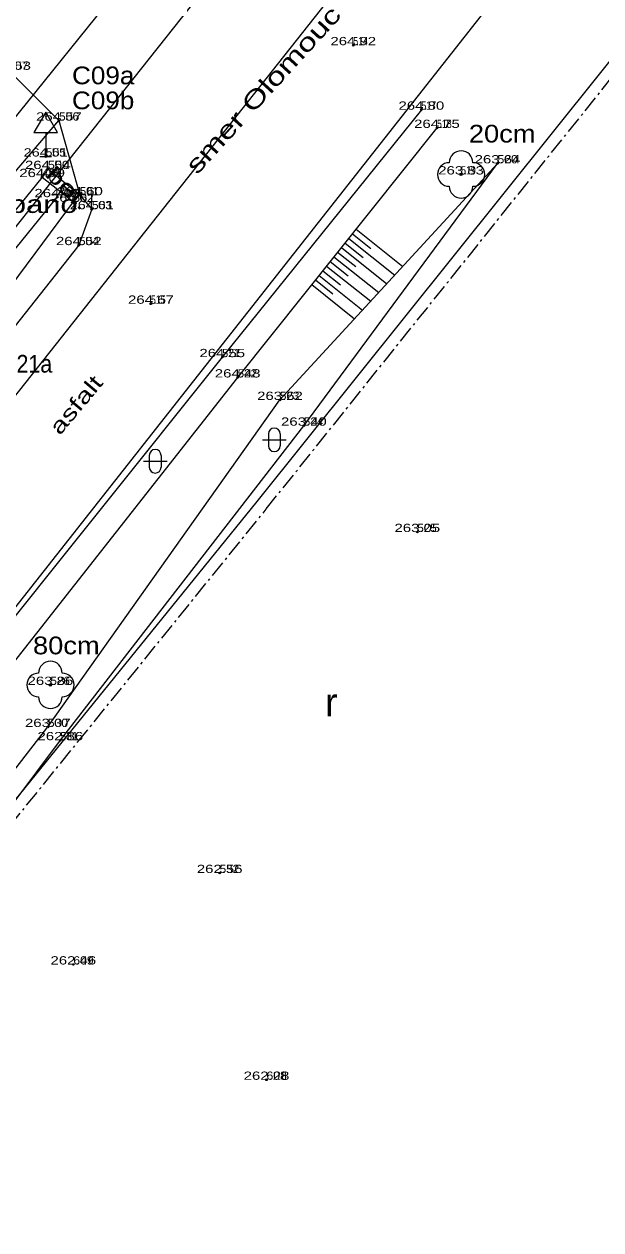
# Model space of a CAD drawing. Extents: x -568530 to -568223, y -1154101 to -1153740.
# Drawn here: x -568358.2 to -568333.8, y -1153886.3 to -1153835.3 of the extents above; entities that cross this region are included whole.
import ezdxf
from ezdxf.enums import TextEntityAlignment as Align

# ---------------------------------------------------------------- set-up
doc = ezdxf.new("R2010")
doc.units = 0
doc.header["$LTSCALE"] = 0.14
doc.header["$PDMODE"] = 32
doc.header["$PDSIZE"] = 0.07
doc.linetypes.add('DOT_DASHED', pattern=[7.7, 5, -1.2, 0.3, -1.2])
for name, color, linetype, lineweight in [('1', 7, 'Continuous', 25), ('10', 7, 'Continuous', 13), ('11', 7, 'Continuous', 13), ('12', 7, 'Continuous', 13), ('14', 7, 'Continuous', 13), ('15', 7, 'Continuous', 13), ('22', 7, 'Continuous', 13), ('23', 7, 'Continuous', 13), ('34', 7, 'Continuous', 13), ('36', 7, 'Continuous', 13), ('4', 7, 'Continuous', 25), ('42', 7, 'Continuous', 13), ('6', 7, 'DOT_DASHED', 25)]:
    doc.layers.add(name, color=color, linetype=linetype, lineweight=lineweight)
doc.layers.add('13', color=7, linetype='Continuous')
doc.layers.add('40', color=7, linetype='Continuous')

msp = doc.modelspace()

# ---------------------------------------------------------------- linework, layer by layer
at = {"layer": '1'}
for points in [[(-568412.56, -1153907.8), (-568411.98, -1153907.12), (-568411.65, -1153906.73), (-568402.04, -1153895.41), (-568393.94, -1153886.59), (-568382.28, -1153873.78), (-568334.11, -1153813.06), (-568281.93, -1153748.16)], [(-568397.85, -1153916.62), (-568348.36, -1153855.52), (-568306.73, -1153803.52), (-568266.23, -1153754.08)], [(-568359.48, -1153840.35), (-568353.42, -1153832.84), (-568366.2, -1153822.48), (-568392.31, -1153801.22), (-568392.76, -1153800.31), (-568393.76, -1153795.28)]]:
    msp.add_lwpolyline(points, dxfattribs=at)
at = {"layer": '10'}
for points in [[(-568358.89, -1153837.25), (-568356.74, -1153839.4), (-568355.85, -1153842.56), (-568355.35, -1153843.15), (-568355.9, -1153844.67)], [(-568341.41, -1153838.94), (-568349.83, -1153849.41), (-568360.25, -1153862.43), (-568369.78, -1153874.42), (-568378.19, -1153884.73), (-568386.01, -1153894.27), (-568392.67, -1153902.27), (-568398.22, -1153909.37), (-568401.79, -1153914.15), (-568403.6, -1153916.28)], [(-568355.9, -1153844.67), (-568366.36, -1153857.91), (-568375.7, -1153869.7), (-568384.23, -1153880.16)]]:
    msp.add_lwpolyline(points, dxfattribs=at)
at = {"layer": '11'}
msp.add_lwpolyline([(-568381.7, -1153869.78), (-568379.23, -1153866.82), (-568369.76, -1153855.31), (-568359.16, -1153842.23), (-568356.74, -1153839.4)], dxfattribs=at)
msp.add_lwpolyline([(-568356.13, -1153842.84), (-568355.85, -1153842.56), (-568357.21, -1153841.45), (-568357.45, -1153841.79)], close=True, dxfattribs=at)
for p in [(-568344.29, -1153836.21), (-568356.74, -1153839.4), (-568341.41, -1153838.94), (-568340.75, -1153839.71), (-568357.3, -1153840.92), (-568357.21, -1153841.45), (-568338.19, -1153841.21), (-568357.45, -1153841.79), (-568339.73, -1153841.68), (-568356.81, -1153842.64), (-568356.13, -1153842.84), (-568355.85, -1153842.56), (-568355.35, -1153843.15), (-568355.9, -1153844.67), (-568352.85, -1153847.15), (-568349.83, -1153849.41), (-568349.18, -1153850.27), (-568347.39, -1153851.22), (-568346.38, -1153852.31), (-568341.58, -1153856.81), (-568357.1, -1153863.28), (-568357.21, -1153865.06), (-568356.68, -1153865.62), (-568349.94, -1153871.24), (-568356.13, -1153875.11), (-568347.96, -1153879.99)]:
    msp.add_point(p, dxfattribs=at)
at = {"layer": '14'}
for points in [[(-568340.75, -1153839.71), (-568349.18, -1153850.27), (-568359.47, -1153863.33), (-568369.12, -1153875.21), (-568377.44, -1153885.3)], [(-568395.11, -1153912.31), (-568389.39, -1153905.01), (-568382.04, -1153896.57), (-568374.93, -1153888.14), (-568366.7, -1153877.32), (-568357.21, -1153865.06), (-568347.39, -1153851.22), (-568338.19, -1153841.21)], [(-568357.45, -1153841.79), (-568368.95, -1153855.98), (-568378.18, -1153867.7), (-568386.1, -1153877.81), (-568384.71, -1153879.25), (-568384.84, -1153877.95), (-568386.1, -1153877.81)], [(-568384.84, -1153877.95), (-568377.13, -1153868.43), (-568368.18, -1153856.68), (-568356.81, -1153842.64)], [(-568384.71, -1153879.25), (-568376.25, -1153869.09), (-568366.96, -1153857.43), (-568356.13, -1153842.84)]]:
    msp.add_lwpolyline(points, dxfattribs=at)
at = {"layer": '15'}
for p, q in [((-568344.482, -1153844.385), (-568342.536, -1153845.939)), ((-568344.326, -1153844.19), (-568343.542, -1153844.815)), ((-568344.17, -1153843.994), (-568342.197, -1153845.57)), ((-568344.95, -1153844.971), (-568344.188, -1153845.58)), ((-568344.794, -1153844.776), (-568342.875, -1153846.308)), ((-568344.638, -1153844.58), (-568343.865, -1153845.197)), ((-568345.262, -1153845.362), (-568344.511, -1153845.962)), ((-568345.106, -1153845.167), (-568343.214, -1153846.677)), ((-568345.73, -1153845.948), (-568343.893, -1153847.415)), ((-568345.574, -1153845.753), (-568344.834, -1153846.344)), ((-568345.418, -1153845.557), (-568343.553, -1153847.046)), ((-568346.042, -1153846.339), (-568344.232, -1153847.784)), ((-568345.886, -1153846.143), (-568345.156, -1153846.726))]:
    msp.add_line(p, q, dxfattribs=at)
at = {"layer": '22'}
for centre in [(-568339.73, -1153841.68), (-568357.1, -1153863.28)]:
    msp.add_circle(centre, 0.05, dxfattribs=at)
for centre, start, end in [((-568339.73, -1153841.18), 0, 180), ((-568340.23, -1153841.68), 90, 270), ((-568339.23, -1153841.68), 270, 90), ((-568339.73, -1153842.18), 180, 0), ((-568357.1, -1153862.78), 0, 180), ((-568357.6, -1153863.28), 90, 270), ((-568356.6, -1153863.28), 270, 90), ((-568357.1, -1153863.78), 180, 0)]:
    msp.add_arc(centre, 0.5, start, end, dxfattribs=at)
at = {"layer": '23'}
msp.add_lwpolyline([(-568354.04, -1153929.41), (-568364.61, -1153923.44), (-568379.16, -1153915.86), (-568390.37, -1153909.46), (-568387.81, -1153906.15), (-568381.36, -1153897.16), (-568374.28, -1153888.42), (-568365.82, -1153877.84), (-568356.68, -1153865.62), (-568346.38, -1153852.31), (-568338.19, -1153841.21)], dxfattribs=at)
at = {"layer": '34'}
for p, q in [((-568357.3, -1153839.902), (-568357.3, -1153840.92)), ((-568357.55, -1153840.92), (-568357.05, -1153840.92))]:
    msp.add_line(p, q, dxfattribs=at)
msp.add_lwpolyline([(-568357.8, -1153839.902), (-568356.8, -1153839.902), (-568357.3, -1153839.036)], close=True, dxfattribs=at)
at = {"layer": '36'}
for p, q in [((-568348.132, -1153852.907), (-568347.132, -1153852.907)), ((-568347.882, -1153852.657), (-568347.882, -1153853.157)), ((-568347.382, -1153852.657), (-568347.382, -1153853.157)), ((-568352.918, -1153853.565), (-568352.918, -1153854.065)), ((-568352.418, -1153853.565), (-568352.418, -1153854.065)), ((-568353.168, -1153853.815), (-568352.168, -1153853.815))]:
    msp.add_line(p, q, dxfattribs=at)
for centre, start, end in [((-568347.6321, -1153852.6587), 0, 180), ((-568352.6682, -1153853.5671), 0, 180), ((-568347.6321, -1153853.1587), 180, 0), ((-568352.6682, -1153854.0671), 180, 0)]:
    msp.add_arc(centre, 0.25, start, end, dxfattribs=at)
at = {"layer": '4'}
for points in [[(-568271.05, -1153741.89), (-568310.68, -1153791.16), (-568343.12, -1153831.47), (-568381.67, -1153880.2), (-568407.5, -1153911.44)], [(-568401.59, -1153914.63), (-568397.99, -1153910.05), (-568332.4, -1153826.72), (-568306.48, -1153794.28), (-568270.78, -1153751.53)]]:
    msp.add_lwpolyline(points, dxfattribs=at)
at = {"layer": '6'}
for p, q in [((-568347.97, -1153855.83), (-568306.34, -1153803.83)), ((-568390.25, -1153908.12), (-568347.97, -1153855.84))]:
    msp.add_line(p, q, dxfattribs=at)

# ---------------------------------------------------------------- texts
at = {"layer": '12'}
for s, width, p in [('264.92', 1.35, (-568344.29, -1153836.21)), ('264.53', 1.35, (-568358.89, -1153837.25)), ('264.80', 1.35, (-568341.4095, -1153838.94)), ('264.57', 1.35, (-568356.74, -1153839.4)), ('264.75', 1.35, (-568340.7505, -1153839.71)), ('264.51', 1.3, (-568357.3, -1153840.92)), ('263.64', 1.35, (-568338.19, -1153841.21)), ('264.54', 1.35, (-568357.21, -1153841.45)), ('263.83', 1.35, (-568339.73, -1153841.68)), ('264.49', 1.35, (-568357.45, -1153841.79)), ('264.09', 1.35, (-568356.81, -1153842.64)), ('264.60', 1.35, (-568355.8495, -1153842.56)), ('264.61', 1.3, (-568356.13, -1153842.84)), ('264.61', 1.3, (-568355.35, -1153843.15)), ('264.52', 1.35, (-568355.9, -1153844.67)), ('264.67', 1.35, (-568352.85, -1153847.15)), ('264.55', 1.35, (-568349.8305, -1153849.41)), ('264.48', 1.35, (-568349.18, -1153850.27)), ('263.62', 1.35, (-568347.39, -1153851.22)), ('263.40', 1.35, (-568346.3795, -1153852.31)), ('263.05', 1.35, (-568341.5805, -1153856.81)), ('263.86', 1.35, (-568357.1, -1153863.28)), ('263.07', 1.35, (-568357.21, -1153865.06)), ('262.86', 1.35, (-568356.68, -1153865.62)), ('262.56', 1.35, (-568349.94, -1153871.24)), ('262.46', 1.35, (-568356.13, -1153875.11)), ('262.28', 1.35, (-568347.96, -1153879.99))]:
    msp.add_text(s, height=0.35, dxfattribs=dict(at, width=width)).set_placement(p, align=Align.CENTER)
at = {"layer": '13'}
for s, width, p in [('514', 0.8, (-568344.29, -1153836.21)), ('507', 1.1, (-568358.89, -1153837.25)), ('517', 0.8, (-568341.41, -1153838.94)), ('506', 1.1, (-568356.74, -1153839.4)), ('518', 0.8, (-568340.75, -1153839.71)), ('505', 1.1, (-568357.3, -1153840.92)), ('520', 1.1, (-568338.19, -1153841.21)), ('500', 1.15, (-568357.21, -1153841.45)), ('519', 0.8, (-568339.73, -1153841.68)), ('499', 1.05, (-568357.45, -1153841.79)), ('498', 1.05, (-568356.81, -1153842.64)), ('502', 1.1, (-568356.13, -1153842.84)), ('503', 1.1, (-568355.35, -1153843.15)), ('504', 1.1, (-568355.9, -1153844.67)), ('515', 0.8, (-568352.85, -1153847.15)), ('521', 0.95, (-568349.83, -1153849.41)), ('522', 1.05, (-568349.18, -1153850.27)), ('523', 1.05, (-568347.39, -1153851.22)), ('524', 1.05, (-568346.38, -1153852.31)), ('525', 1.05, (-568341.58, -1153856.81)), ('526', 1.05, (-568357.1, -1153863.28)), ('530', 1.1, (-568357.21, -1153865.06)), ('531', 0.95, (-568356.68, -1153865.62)), ('532', 1.05, (-568349.94, -1153871.24)), ('609', 1.1, (-568356.13, -1153875.11)), ('608', 1.1, (-568347.96, -1153879.99))]:
    msp.add_text(s, height=0.35, dxfattribs=dict(at, width=width)).set_placement(p)
msp.add_text('501', height=0.35, dxfattribs=at).set_placement((-568355.85, -1153842.56))
at = {"layer": '36'}
msp.add_text('r', height=1.2, dxfattribs=at).set_placement((-568345.2195, -1153864.609), align=Align.CENTER)
at = {"layer": '40'}
for s, rotation, width, p in [('bet.', 315.978, 1.5, (-568357.348, -1153841.741)), ('asfalt', 50.073, 1.4, (-568356.702, -1153852.75))]:
    msp.add_text(s, height=0.65, rotation=rotation, dxfattribs=dict(at, width=width)).set_placement(p)
at = {"layer": '42', "width": 1.4}
msp.add_text('smer Olomouc', height=0.75, rotation=47.66, dxfattribs=at).set_placement((-568347.8222, -1153838.3476), align=Align.CENTER)
at = {"layer": '42'}
for s, width, p in [('C09a', 1.1, (-568354.8665, -1153837.863)), ('C09b', 1.1, (-568354.869, -1153838.92)), ('20cm', 1.15, (-568337.991, -1153840.328)), ('zasypano', 1.3, (-568358.7435, -1153843.307)), ('B21a', 0.9, (-568358.0795, -1153850.064)), ('80cm', 1.15, (-568356.427, -1153861.984))]:
    msp.add_text(s, height=0.75, dxfattribs=dict(at, width=width)).set_placement(p, align=Align.CENTER)

doc.saveas('drawing.dxf')
